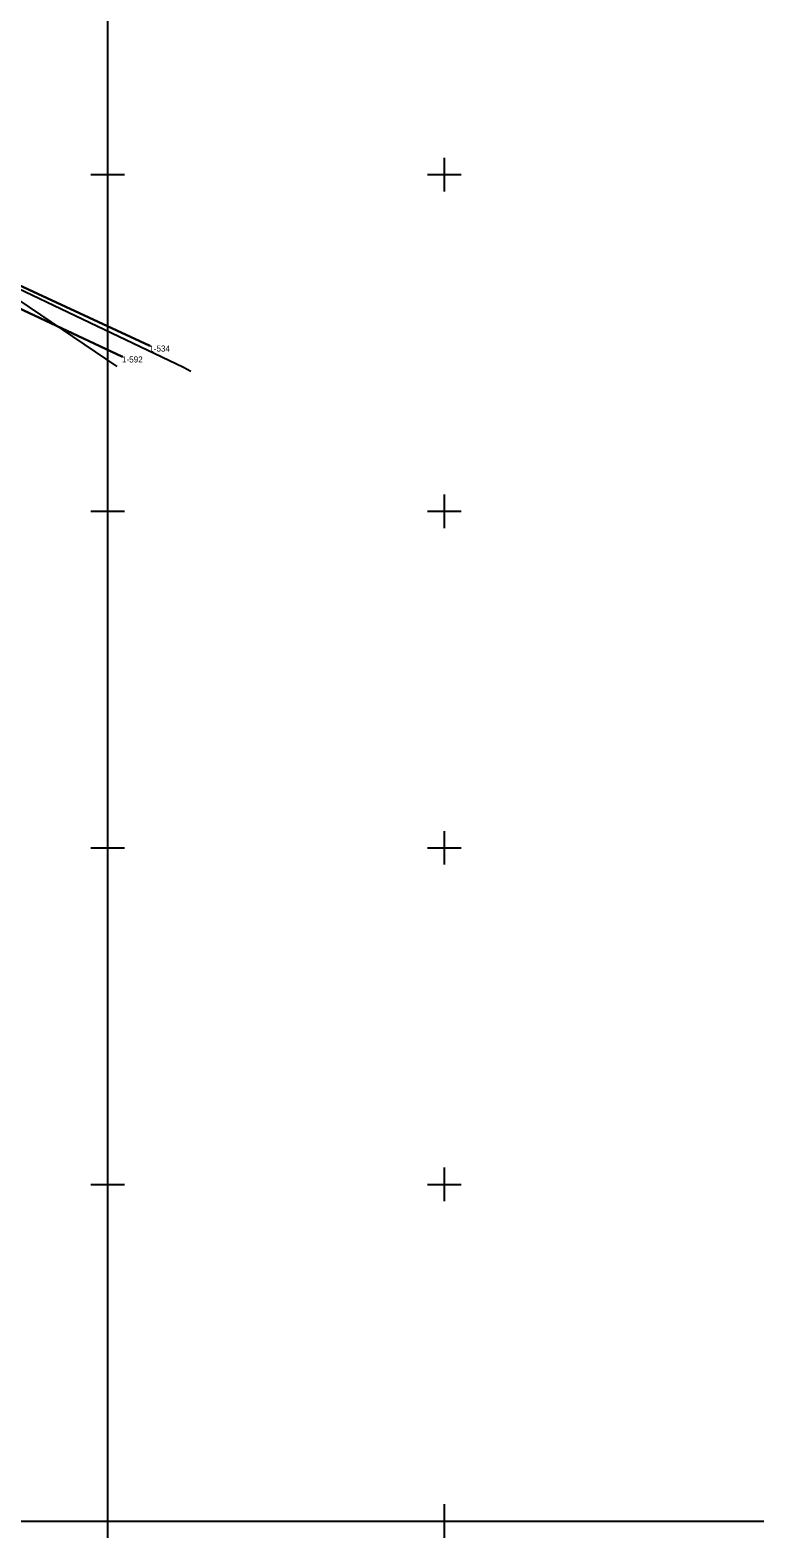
# Model space of a CAD drawing. Extents: x 5598798 to 5599616, y 5661498 to 5662453.
# Drawn here: x 5599188.5 to 5599296.1, y 5661497.5 to 5661721.5 of the extents above; entities that cross this region are included whole.
import ezdxf

# ---------------------------------------------------------------- set-up
doc = ezdxf.new("R2010")
doc.units = 0
for name, color, linetype in [('Dzialki', 7, 'Continuous'), ('Kontury', 7, 'Continuous'), ('KTPL_L_0', 7, 'Continuous'), ('Numery_punktow', 7, 'Continuous'), ('Podzial_sekcyjny_krzyze', 7, 'Continuous'), ('Podzial_sekcyjny_podstawowy', 7, 'Continuous'), ('Punkty', 7, 'Continuous'), ('SUPK_L_1', 7, 'Continuous'), ('Uzytki', 7, 'Continuous')]:
    doc.layers.add(name, color=color, linetype=linetype)

# ---------------------------------------------------------------- blocks, each defined once
blk = doc.blocks.new('GRO')
blk.add_circle((0, 0), 0.045)

msp = doc.modelspace()

# ---------------------------------------------------------------- linework, layer by layer
at = {"layer": 'Dzialki'}
for p, q in [((5599206.16, 5661674.62), (5599162.48, 5661694.84)), ((5599202.11, 5661673), (5599160.79, 5661692.35))]:
    msp.add_line(p, q, dxfattribs=at)
at = {"layer": 'Kontury'}
msp.add_line((5599206.17, 5661674.62), (5599162.48, 5661694.84), dxfattribs=at)
at = {"layer": 'KTPL_L_0'}
msp.add_line((5599163.81, 5661696.88), (5599201.36, 5661671.51), dxfattribs=at)
at = {"layer": 'Podzial_sekcyjny_krzyze'}
for p, q in [((5599200, 5661697.5), (5599200, 5661702.5)), ((5599250, 5661697.5), (5599250, 5661702.5)), ((5599197.5, 5661700), (5599202.5, 5661700)), ((5599247.5, 5661700), (5599252.5, 5661700)), ((5599200, 5661647.5), (5599200, 5661652.5)), ((5599250, 5661647.5), (5599250, 5661652.5)), ((5599197.5, 5661650), (5599202.5, 5661650)), ((5599247.5, 5661650), (5599252.5, 5661650)), ((5599200, 5661597.5), (5599200, 5661602.5)), ((5599250, 5661597.5), (5599250, 5661602.5)), ((5599197.5, 5661600), (5599202.5, 5661600)), ((5599247.5, 5661600), (5599252.5, 5661600)), ((5599200, 5661547.5), (5599200, 5661552.5)), ((5599250, 5661547.5), (5599250, 5661552.5)), ((5599197.5, 5661550), (5599202.5, 5661550)), ((5599247.5, 5661550), (5599252.5, 5661550)), ((5599200, 5661497.5), (5599200, 5661502.5)), ((5599250, 5661497.5), (5599250, 5661502.5)), ((5599197.5, 5661500), (5599202.5, 5661500)), ((5599247.5, 5661500), (5599252.5, 5661500))]:
    msp.add_line(p, q, dxfattribs=at)
at = {"layer": 'Podzial_sekcyjny_podstawowy'}
for p, q in [((5599200, 5661500), (5599200, 5661750)), ((5598800, 5661500), (5599200, 5661500)), ((5599200, 5661500), (5599600, 5661500))]:
    msp.add_line(p, q, dxfattribs=at)
at = {"layer": 'SUPK_L_1'}
for p, q in [((5599211.26, 5661671.34), (5599174.39, 5661688.91)), ((5599212.36, 5661670.78), (5599211.26, 5661671.34))]:
    msp.add_line(p, q, dxfattribs=at)
at = {"layer": 'Uzytki'}
for p, q in [((5599162.48, 5661694.84), (5599206.17, 5661674.62)), ((5599160.79, 5661692.35), (5599202.11, 5661673))]:
    msp.add_line(p, q, dxfattribs=at)

# ---------------------------------------------------------------- block references
at = {"layer": 'Punkty'}
for p in [(5599202.11, 5661673), (5599206.16, 5661674.62)]:
    msp.add_blockref('GRO', p, dxfattribs=at)

# ---------------------------------------------------------------- texts
at = {"layer": 'Numery_punktow'}
for s, p in [('1-592', (5599202.11, 5661672.1)), ('1-534', (5599206.16, 5661673.72))]:
    msp.add_text(s, height=0.9, dxfattribs=at).set_placement(p)

doc.saveas('drawing.dxf')
